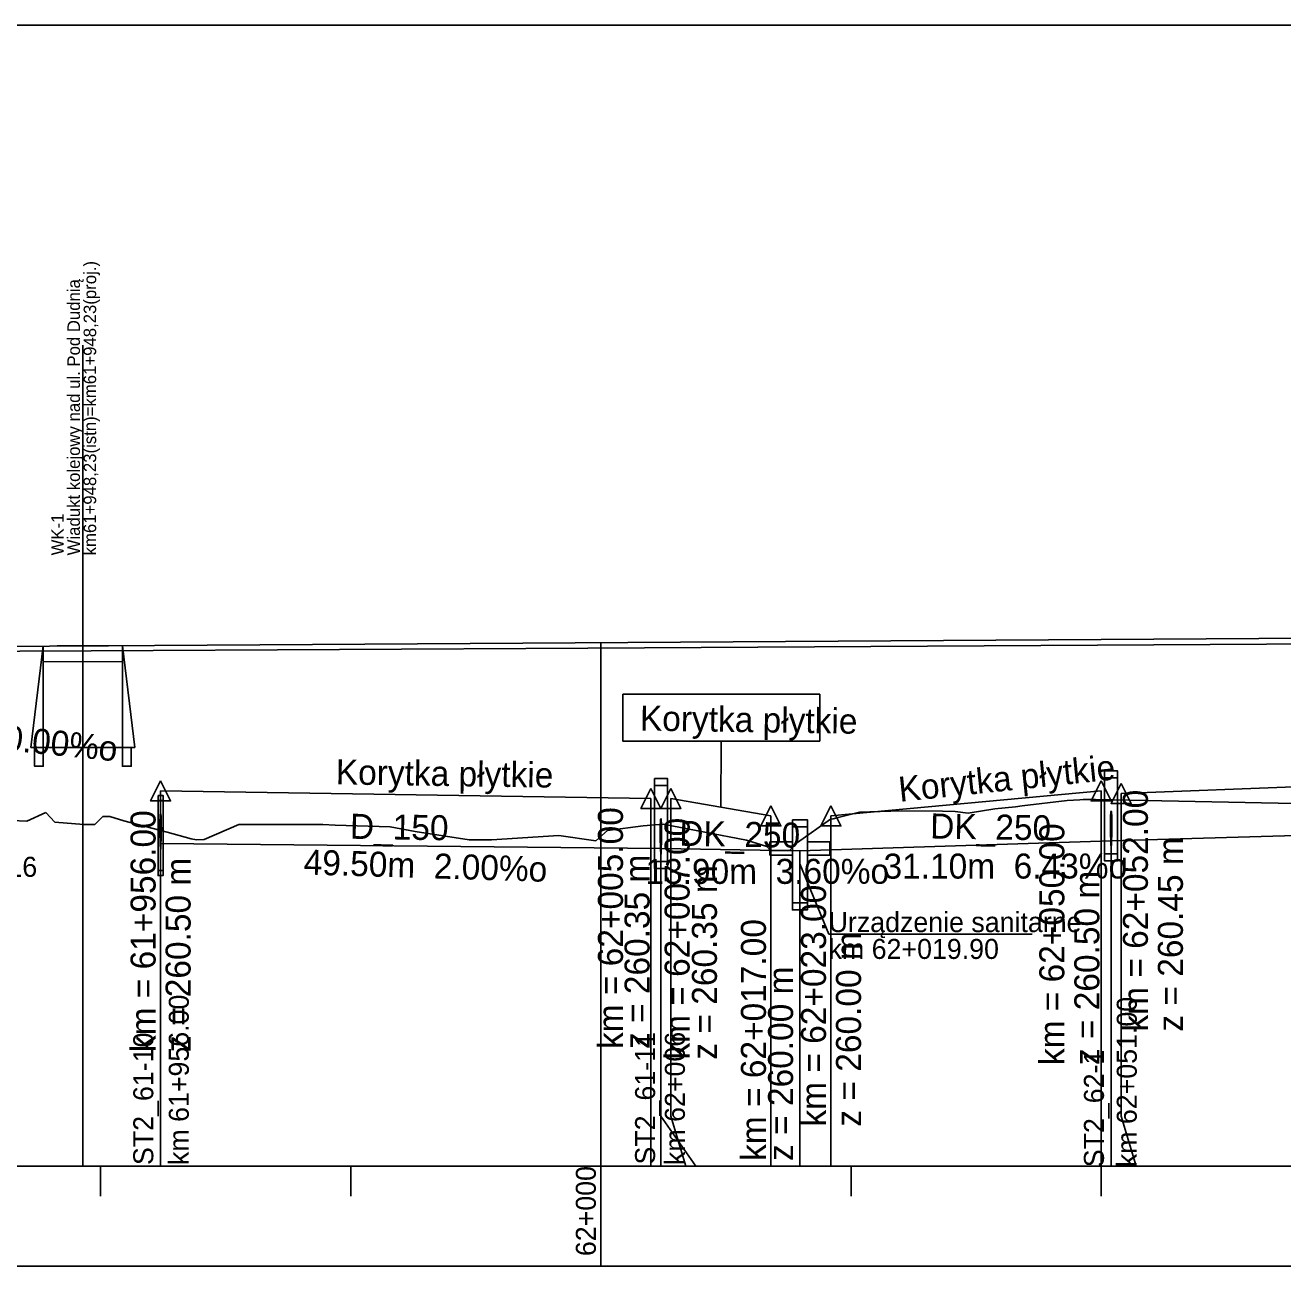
# Model space of a CAD drawing. Extents: x 6445630 to 6518227, y 5499240 to 5511716.
# Drawn here: x 6461173.7 to 6461299.4, y 5508580.5 to 5508705.3 of the extents above; entities that cross this region are included whole.
import ezdxf

# ---------------------------------------------------------------- set-up
doc = ezdxf.new("R2010")
doc.units = 0
for name, color, linetype in [('TOR_PROF-drenaze', 7, 'Continuous'), ('TOR_PROF-drenokolektory', 7, 'Continuous'), ('TOR_PROF-obiekty+opisy', 7, 'Continuous'), ('TOR_PROF-opisy glowne', 7, 'Continuous'), ('TOR_PROF-opisy pomocnicze', 7, 'Continuous'), ('TOR_PROF-rowy otwarte', 7, 'Continuous'), ('TOR_PROF-studnie i osadniki', 7, 'Continuous'), ('TOR_PROF-tabelka-pochylenia proj T1', 7, 'Continuous'), ('TOR_PROF-tor istniejacy T2', 7, 'Continuous'), ('TOR_PROF-tor projektowany', 7, 'Continuous'), ('TOR_PROF-uklad odniesienia', 7, 'Continuous'), ('TOR_PS_ODW-drenaze', 7, 'Continuous'), ('TOR_RAMKI-dodatkowe3', 7, 'Continuous'), ('TOR_RAMKI-MASKA WYCIECIA', 7, 'Continuous')]:
    doc.layers.add(name, color=color, linetype=linetype)

msp = doc.modelspace()

# ---------------------------------------------------------------- linework, layer by layer
at = {"layer": 'TOR_PROF-drenaze'}
for points in [[(6461342.21, 5508625.54), (6461282.21, 5508623.79)], [(6461187.21, 5508623.54), (6461237.21, 5508623.04)], [(6461237.21, 5508623.04), (6461251.11, 5508622.79)]]:
    msp.add_lwpolyline(points, dxfattribs=at)
at = {"layer": 'TOR_PROF-drenokolektory'}
for points in [[(6461187.21, 5508623.54), (6461187.21, 5508596.29), (6461187.21, 5508591.29), (6461187.21, 5508591.29)], [(6461187.21, 5508623.54), (6461187.21, 5508596.29), (6461187.21, 5508591.29), (6461187.21, 5508591.29)], [(6461237.21, 5508623.04), (6461237.21, 5508596.29), (6461237.21, 5508591.29), (6461237.21, 5508591.29)], [(6461237.21, 5508623.04), (6461237.21, 5508596.29), (6461237.21, 5508591.29), (6461237.21, 5508591.29)], [(6461237.21, 5508623.04), (6461237.21, 5508596.29), (6461240.71, 5508591.29), (6461240.71, 5508591.29)], [(6461282.21, 5508623.79), (6461251.11, 5508622.79)], [(6461251.11, 5508622.79), (6461251.11, 5508596.04), (6461251.11, 5508591.29), (6461251.11, 5508591.29)], [(6461251.11, 5508622.79), (6461251.11, 5508596.29), (6461251.11, 5508591.29), (6461251.11, 5508591.29)], [(6461282.21, 5508623.79), (6461282.21, 5508596.29), (6461282.21, 5508591.29), (6461282.21, 5508591.29)]]:
    msp.add_lwpolyline(points, dxfattribs=at)
at = {"layer": 'TOR_PROF-obiekty+opisy'}
for p, q in [((6461179.44, 5508591.29), (6461179.44, 5508673.31)), ((6461174.24, 5508633.12), (6461175.49, 5508643.28)), ((6461175.49, 5508633.12), (6461175.49, 5508643.28)), ((6461176.87, 5508643.28), (6461182.02, 5508643.28)), ((6461183.4, 5508633.12), (6461183.4, 5508643.28)), ((6461184.65, 5508633.12), (6461183.4, 5508643.28)), ((6461183.4, 5508641.69), (6461175.49, 5508641.7)), ((6461174.24, 5508633.12), (6461184.65, 5508633.12)), ((6461250.36, 5508623.7), (6461248.1, 5508623.7)), ((6461248.1, 5508623.7), (6461248.1, 5508622.36)), ((6461251.86, 5508623.7), (6461254.1, 5508623.7)), ((6461254.1, 5508623.7), (6461254.1, 5508622.36)), ((6461250.36, 5508622.36), (6461248.1, 5508622.36)), ((6461251.11, 5508621.49), (6461253.98, 5508614.48)), ((6461251.86, 5508622.36), (6461254.1, 5508622.36)), ((6461253.98, 5508614.48), (6461274.32, 5508614.48))]:
    msp.add_line(p, q, dxfattribs=at)
for points in [[(6461175.49, 5508633.12), (6461175.49, 5508631.25), (6461174.61, 5508631.25), (6461174.61, 5508633.12)], [(6461184.27, 5508633.12), (6461184.27, 5508631.25), (6461183.4, 5508631.25), (6461183.4, 5508633.12)]]:
    msp.add_lwpolyline(points, close=True, dxfattribs=at)
at = {"layer": 'TOR_PROF-opisy glowne'}
msp.add_line((6461243.21, 5508627.16), (6461243.23, 5508633.77), dxfattribs=at)
msp.add_lwpolyline([(6461233.39, 5508638.44), (6461253.08, 5508638.44), (6461253.08, 5508633.77), (6461233.39, 5508633.77)], close=True, dxfattribs=at)
at = {"layer": 'TOR_PROF-opisy pomocnicze'}
for p, q in [((6461187.21, 5508628.79), (6461187.21, 5508601.79)), ((6461236.21, 5508628.04), (6461236.21, 5508601.04)), ((6461238.21, 5508628.04), (6461238.21, 5508601.04)), ((6461281.21, 5508628.79), (6461281.21, 5508601.79)), ((6461283.21, 5508628.54), (6461283.21, 5508601.54)), ((6461248.21, 5508626.29), (6461248.21, 5508599.29)), ((6461254.21, 5508626.29), (6461254.21, 5508599.29))]:
    msp.add_line(p, q, dxfattribs=at)
for points in [[(6461187.21, 5508629.79), (6461188.21, 5508627.79), (6461186.21, 5508627.79)], [(6461236.21, 5508629.04), (6461237.21, 5508627.04), (6461235.21, 5508627.04)], [(6461238.21, 5508629.04), (6461239.21, 5508627.04), (6461237.21, 5508627.04)], [(6461281.21, 5508629.79), (6461282.21, 5508627.79), (6461280.21, 5508627.79)], [(6461283.21, 5508629.54), (6461284.21, 5508627.54), (6461282.21, 5508627.54)], [(6461248.21, 5508627.29), (6461249.21, 5508625.29), (6461247.21, 5508625.29)], [(6461254.21, 5508627.29), (6461255.21, 5508625.29), (6461253.21, 5508625.29)]]:
    msp.add_lwpolyline(points, close=True, dxfattribs=at)
at = {"layer": 'TOR_PROF-rowy otwarte'}
for p, q in [((6461283.21, 5508628.54), (6461341.71, 5508630.79)), ((6461187.21, 5508628.79), (6461236.21, 5508628.04)), ((6461238.21, 5508628.04), (6461248.21, 5508626.29)), ((6461254.21, 5508626.29), (6461281.21, 5508628.79))]:
    msp.add_line(p, q, dxfattribs=at)
for points in [[(6461187.21, 5508628.79), (6461187.21, 5508596.29), (6461187.21, 5508591.29), (6461187.21, 5508591.29)], [(6461231.21, 5508628.12), (6461231.21, 5508596.29), (6461231.21, 5508591.29), (6461231.21, 5508591.29)], [(6461231.21, 5508628.12), (6461231.21, 5508596.29), (6461231.21, 5508591.29), (6461231.21, 5508591.29)], [(6461236.21, 5508628.04), (6461236.21, 5508596.29), (6461236.21, 5508591.29), (6461236.21, 5508591.29)], [(6461236.21, 5508628.04), (6461236.21, 5508596.29), (6461236.21, 5508591.29), (6461236.21, 5508591.29)], [(6461238.21, 5508628.04), (6461238.21, 5508596.29), (6461239.71, 5508591.29), (6461239.71, 5508591.29)], [(6461238.21, 5508628.04), (6461238.21, 5508596.29), (6461239.71, 5508591.29), (6461239.71, 5508591.29)], [(6461281.21, 5508628.79), (6461281.21, 5508596.29), (6461281.21, 5508591.29), (6461281.21, 5508591.29)], [(6461281.21, 5508628.79), (6461281.21, 5508596.29), (6461281.21, 5508591.29), (6461281.21, 5508591.29)], [(6461283.21, 5508628.54), (6461283.21, 5508596.29), (6461284.71, 5508591.29), (6461284.71, 5508591.29)], [(6461283.21, 5508628.54), (6461283.21, 5508596.29), (6461284.71, 5508591.29), (6461284.71, 5508591.29)], [(6461248.21, 5508626.29), (6461248.21, 5508596.29), (6461248.21, 5508591.29), (6461248.21, 5508591.29)], [(6461248.21, 5508626.29), (6461248.21, 5508596.29), (6461248.21, 5508591.29), (6461248.21, 5508591.29)], [(6461254.21, 5508626.29), (6461254.21, 5508596.29), (6461254.21, 5508591.29), (6461254.21, 5508591.29)], [(6461254.21, 5508626.29), (6461254.21, 5508596.29), (6461254.21, 5508591.29), (6461254.21, 5508591.29)], [(6461187.21, 5508623.54), (6461187.21, 5508596.29), (6461187.21, 5508591.29), (6461187.21, 5508591.29)], [(6461237.21, 5508623.04), (6461237.21, 5508596.29), (6461237.21, 5508591.29), (6461237.21, 5508591.29)], [(6461237.21, 5508623.04), (6461237.21, 5508596.29), (6461240.71, 5508591.29), (6461240.71, 5508591.29)], [(6461251.11, 5508622.79), (6461251.11, 5508596.29), (6461251.11, 5508591.29), (6461251.11, 5508591.29)], [(6461282.21, 5508623.79), (6461282.21, 5508596.29), (6461282.21, 5508591.29), (6461282.21, 5508591.29)]]:
    msp.add_lwpolyline(points, dxfattribs=at)
at = {"layer": 'TOR_PROF-studnie i osadniki'}
for p, q in [((6461281.56, 5508630.79), (6461281.56, 5508621.79)), ((6461281.56, 5508630.79), (6461282.86, 5508630.79)), ((6461282.86, 5508630.79), (6461282.86, 5508621.79)), ((6461236.56, 5508630.04), (6461236.56, 5508621.04)), ((6461236.56, 5508630.04), (6461237.86, 5508630.04)), ((6461237.86, 5508630.04), (6461237.86, 5508621.04)), ((6461186.96, 5508628.33), (6461186.96, 5508620.33)), ((6461186.96, 5508628.33), (6461187.46, 5508628.33)), ((6461187.46, 5508628.33), (6461187.46, 5508620.33)), ((6461250.36, 5508625.9), (6461250.36, 5508616.9)), ((6461250.46, 5508625.9), (6461251.76, 5508625.9)), ((6461251.86, 5508625.9), (6461251.86, 5508616.9)), ((6461281.56, 5508621.79), (6461282.86, 5508621.79)), ((6461186.96, 5508620.33), (6461187.46, 5508620.33)), ((6461236.56, 5508621.04), (6461237.86, 5508621.04)), ((6461250.36, 5508616.9), (6461251.86, 5508616.9))]:
    msp.add_line(p, q, dxfattribs=at)
for points in [[(6461281.56, 5508630.79), (6461282.86, 5508630.79), (6461282.86, 5508630.09), (6461281.56, 5508630.09)], [(6461236.56, 5508630.04), (6461237.86, 5508630.04), (6461237.86, 5508629.34), (6461236.56, 5508629.34)], [(6461186.96, 5508628.33), (6461187.46, 5508628.33), (6461187.46, 5508627.83), (6461186.96, 5508627.83)], [(6461250.36, 5508625.9), (6461251.86, 5508625.9), (6461251.86, 5508625.2), (6461250.36, 5508625.2)], [(6461236.56, 5508621.74), (6461237.86, 5508621.74), (6461237.86, 5508621.04), (6461236.56, 5508621.04)], [(6461281.56, 5508622.49), (6461282.86, 5508622.49), (6461282.86, 5508621.79), (6461281.56, 5508621.79)], [(6461186.96, 5508620.83), (6461187.46, 5508620.83), (6461187.46, 5508620.33), (6461186.96, 5508620.33)], [(6461250.36, 5508617.6), (6461251.86, 5508617.6), (6461251.86, 5508616.9), (6461250.36, 5508616.9)]]:
    msp.add_lwpolyline(points, close=True, dxfattribs=at)
at = {"layer": 'TOR_PROF-tabelka-pochylenia proj T1'}
msp.add_lwpolyline([(6452331.21, 5508571.29), (6462731.21, 5508571.29), (6462731.21, 5508581.29), (6452331.21, 5508581.29)], close=True, dxfattribs=at)
at = {"layer": 'TOR_PROF-tor istniejacy T2'}
msp.add_lwpolyline([(6461480.33, 5508644.34), (6461430.88, 5508644.14), (6461380.73, 5508643.89), (6461331.54, 5508643.64), (6461280.86, 5508643.34), (6461229.91, 5508643.04), (6461180.28, 5508642.79), (6461130.45, 5508642.54), (6461080.72, 5508642.24), (6461030.67, 5508641.99), (6460980.62, 5508641.74), (6460928.07, 5508641.44), (6460879.61, 5508641.04), (6460836.6, 5508640.89), (6460803.37, 5508640.79)], dxfattribs=at)
at = {"layer": 'TOR_PROF-tor projektowany'}
msp.add_line((6460751.21, 5508640.59), (6462357.21, 5508650.69), dxfattribs=at)
msp.add_line((6460751.21, 5508640.59), (6462357.21, 5508650.69), dxfattribs=at)
msp.add_lwpolyline([(6461231.21, 5508643.61), (6461231.21, 5508596.29), (6461231.21, 5508591.29), (6461231.21, 5508591.29)], dxfattribs=at)
msp.add_lwpolyline([(6461231.21, 5508643.61), (6461231.21, 5508596.29), (6461231.21, 5508591.29), (6461231.21, 5508591.29)], dxfattribs=at)
at = {"layer": 'TOR_PROF-uklad odniesienia'}
for p, q in [((6452331.21, 5508591.29), (6462731.21, 5508591.29)), ((6452331.21, 5508591.29), (6462731.21, 5508591.29)), ((6461181.21, 5508588.29), (6461181.21, 5508591.29)), ((6461181.21, 5508588.29), (6461181.21, 5508591.29)), ((6461206.21, 5508588.29), (6461206.21, 5508591.29)), ((6461206.21, 5508588.29), (6461206.21, 5508591.29)), ((6461231.21, 5508581.29), (6461231.21, 5508591.29)), ((6461231.21, 5508581.29), (6461231.21, 5508591.29)), ((6461256.21, 5508588.29), (6461256.21, 5508591.29)), ((6461256.21, 5508588.29), (6461256.21, 5508591.29)), ((6461281.21, 5508588.29), (6461281.21, 5508591.29)), ((6461281.21, 5508588.29), (6461281.21, 5508591.29))]:
    msp.add_line(p, q, dxfattribs=at)
at = {"layer": 'TOR_PS_ODW-drenaze'}
for p, q in [((6461187.21, 5508623.54), (6461187.21, 5508602.66)), ((6461237.21, 5508623.04), (6461237.21, 5508602.16)), ((6461282.21, 5508623.79), (6461282.21, 5508602.91))]:
    msp.add_line(p, q, dxfattribs=at)
for centre, major_axis in [((6461187.21, 5508625.04), (0, 1.5)), ((6461282.21, 5508625.29), (0, 1.5)), ((6461237.21, 5508624.54), (0, 1.5)), ((6461187.21, 5508623.54), (0, -0.6)), ((6461282.21, 5508623.79), (0, -0.6)), ((6461237.21, 5508623.04), (0, -0.6))]:
    msp.add_ellipse(centre, major_axis=major_axis, ratio=0.05, dxfattribs=at)
at = {"layer": 'TOR_RAMKI-dodatkowe3'}
for p, q in [((6461273.31, 5508627.28), (6461277.81, 5508627.83)), ((6461277.81, 5508627.83), (6461279.07, 5508627.89)), ((6461279.07, 5508627.89), (6461279.4, 5508627.93)), ((6461279.4, 5508627.93), (6461280.66, 5508627.93)), ((6461280.66, 5508627.93), (6461305.17, 5508627.44)), ((6461173.84, 5508625.76), (6461175.73, 5508626.63)), ((6461175.73, 5508626.63), (6461176.64, 5508625.65)), ((6461254.92, 5508626.14), (6461257.05, 5508626.68)), ((6461257.05, 5508626.68), (6461261.23, 5508626.79)), ((6461261.23, 5508626.79), (6461265.36, 5508626.75)), ((6461265.36, 5508626.75), (6461266.62, 5508626.73)), ((6461266.62, 5508626.73), (6461267.92, 5508626.58)), ((6461267.92, 5508626.58), (6461270.58, 5508626.98)), ((6461270.58, 5508626.98), (6461272.64, 5508627.2)), ((6461272.64, 5508627.2), (6461273.31, 5508627.28)), ((6461172.35, 5508625.82), (6461173.84, 5508625.76)), ((6461176.64, 5508625.65), (6461179.54, 5508625.42)), ((6461179.54, 5508625.42), (6461180.63, 5508625.44)), ((6461180.63, 5508625.44), (6461181.43, 5508626.24)), ((6461181.43, 5508626.24), (6461182.15, 5508626.24)), ((6461182.15, 5508626.24), (6461183.52, 5508625.79)), ((6461183.52, 5508625.79), (6461187.87, 5508624.65)), ((6461191.56, 5508623.92), (6461195.02, 5508625.43)), ((6461195.02, 5508625.43), (6461203.44, 5508625.43)), ((6461203.44, 5508625.43), (6461204.67, 5508625.38)), ((6461204.67, 5508625.38), (6461210.17, 5508625.2)), ((6461231.86, 5508624.82), (6461235.45, 5508625.3)), ((6461235.45, 5508625.3), (6461237.43, 5508625.45)), ((6461237.43, 5508625.45), (6461245.77, 5508623.88)), ((6461250.85, 5508623.63), (6461254.16, 5508625.95)), ((6461254.16, 5508625.95), (6461254.42, 5508625.99)), ((6461254.42, 5508625.99), (6461254.92, 5508626.14)), ((6461187.87, 5508624.65), (6461190.27, 5508624.01)), ((6461190.27, 5508624.01), (6461190.81, 5508623.89)), ((6461210.17, 5508625.2), (6461212.66, 5508624.74)), ((6461212.66, 5508624.74), (6461218.05, 5508623.91)), ((6461220.29, 5508623.9), (6461227, 5508624.32)), ((6461227, 5508624.32), (6461230.72, 5508623.79)), ((6461230.72, 5508623.79), (6461231.86, 5508624.82)), ((6461190.81, 5508623.89), (6461191.56, 5508623.92)), ((6461218.05, 5508623.91), (6461220.29, 5508623.9)), ((6461245.77, 5508623.88), (6461247.79, 5508623.24)), ((6461247.79, 5508623.24), (6461248.15, 5508622.82)), ((6461248.15, 5508622.82), (6461250.06, 5508622.85)), ((6461250.06, 5508622.85), (6461250.85, 5508623.63))]:
    msp.add_line(p, q, dxfattribs=at)
at = {"layer": 'TOR_RAMKI-MASKA WYCIECIA'}
msp.add_lwpolyline([(6460741.75, 5508418.29), (6462761.75, 5508418.29), (6462761.75, 5508705.29), (6460741.75, 5508705.29)], close=True, dxfattribs=at)

# ---------------------------------------------------------------- texts
at = {"layer": 'TOR_PROF-drenaze'}
for s, rotation, p in [('10.00m  20.00%o  ', 354.2894, (6461156.7, 5508634.34)), ('D_150  ', 359.0503, (6461206.12, 5508624.01)), ('DK_250  ', 359.0503, (6461264.11, 5508624.04)), ('DK_250  ', 359.0503, (6461239.03, 5508623.31)), ('49.50m  2.00%o  ', 358.264, (6461201.48, 5508620.44)), ('13.90m  3.60%o  ', 0.0409, (6461235.67, 5508619.49)), ('31.10m  6.43%o  ', 0.0409, (6461259.46, 5508620.02))]:
    msp.add_text(s, height=2.5, rotation=rotation, dxfattribs=at).set_placement(p)
at = {"layer": 'TOR_PROF-obiekty+opisy'}
for s, p in [('km61+948,23(istn)=km61+948,23(proj.)', (6461180.77, 5508652.32)), ('Wiadukt kolejowy nad ul. Pod Dudnią ', (6461179.15, 5508652.32)), ('WK-1', (6461177.53, 5508652.32))]:
    msp.add_text(s, height=1.25, rotation=90, dxfattribs=at).set_placement(p)
at = {"layer": 'TOR_PROF-opisy glowne'}
for s, rotation, p in [('Wylot do St2_61-9 =261.16', 0.4945, (6461142.4, 5508619.93)), ('km 61+956.00', 90, (6461190.03, 5508591.41)), ('km 62+051.00', 90, (6461284.77, 5508591.19)), ('ST2_61-10', 90, (6461186.48, 5508591.41)), ('ST2_61-11', 90, (6461236.63, 5508591.46)), ('km 62+006', 90, (6461239.61, 5508591.41)), ('ST2_62-1', 90, (6461281.49, 5508591.19))]:
    msp.add_text(s, height=2, rotation=rotation, dxfattribs=at).set_placement(p)
at = {"layer": 'TOR_PROF-opisy pomocnicze'}
for s, rotation, p in [('Korytka płytkie', 359.1406, (6461235.1, 5508634.82)), ('Korytka płytkie', 359.1406, (6461204.71, 5508629.44)), ('Korytka płytkie', 5.9373, (6461261.09, 5508627.69)), ('km = 62+052.00', 90, (6461285.88, 5508604.74)), ('km = 61+956.00', 90, (6461186.71, 5508602.69)), ('km = 62+005.00', 90, (6461233.42, 5508603)), ('km = 62+007.00', 90, (6461240.08, 5508601.94)), ('km = 62+050.00', 90, (6461277.53, 5508601.39)), ('z = 260.45 m', 90, (6461289.38, 5508604.74)), ('z = 260.50 m', 90, (6461190.21, 5508602.69)), ('z = 260.35 m', 90, (6461236.08, 5508603)), ('z = 260.35 m', 90, (6461242.81, 5508601.94)), ('z = 260.50 m', 90, (6461281.03, 5508601.39)), ('km = 62+023.00', 90, (6461253.71, 5508595.25)), ('km = 62+017.00', 90, (6461247.71, 5508591.82)), ('z = 260.00 m', 90, (6461257.21, 5508595.25)), ('z = 260.00 m', 90, (6461250.42, 5508591.82))]:
    msp.add_text(s, height=2.5, rotation=rotation, dxfattribs=at).set_placement(p)
for s, p in [('Urządzenie sanitarne', (6461253.97, 5508614.68)), ('km 62+019.90', (6461253.97, 5508612))]:
    msp.add_text(s, height=2, dxfattribs=at).set_placement(p)
at = {"layer": 'TOR_PROF-uklad odniesienia'}
msp.add_text('62+000', height=2, rotation=90, dxfattribs=at).set_placement((6461230.71, 5508582.31))
msp.add_text('62+000', height=2, rotation=90, dxfattribs=at).set_placement((6461230.71, 5508582.31))

doc.saveas('drawing.dxf')
